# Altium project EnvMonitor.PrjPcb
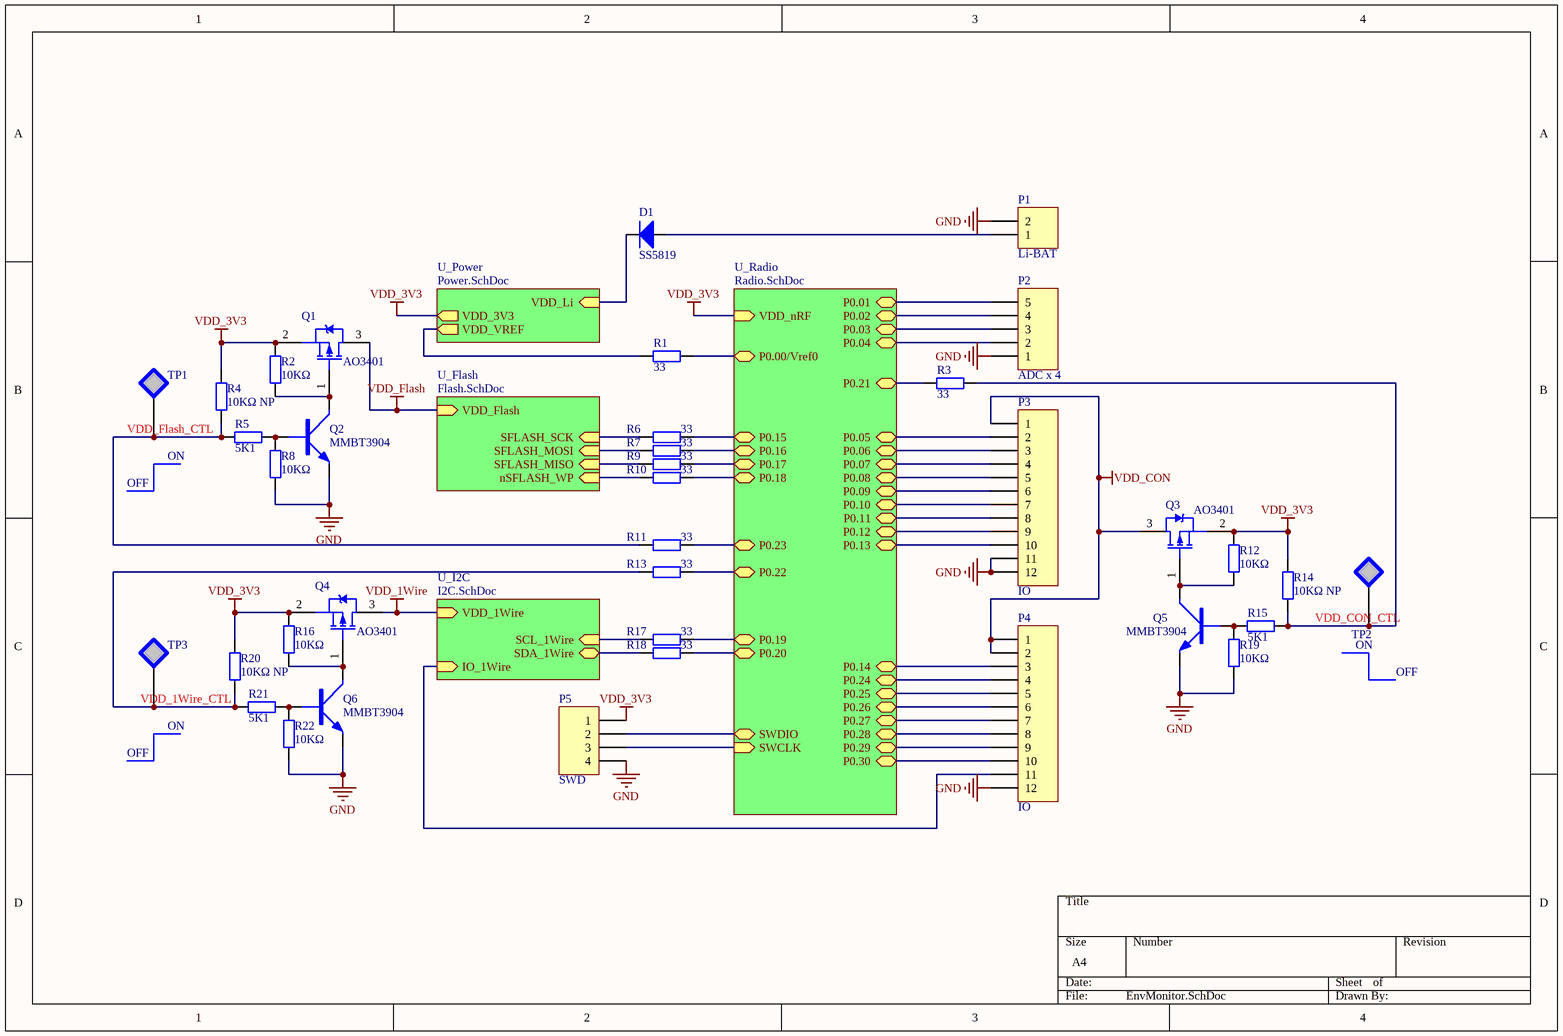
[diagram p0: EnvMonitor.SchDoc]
5 sheets, 85 parts. Net scope: hierarchical (ports join the sheet entries above them; power ports are global).
Sheets:
  EnvMonitor.SchDoc
    U_Radio = Radio.SchDoc
    U_Flash = Flash.SchDoc
    U_Power = Power.SchDoc
    U_I2C = I2C.SchDoc

## Sheet EnvMonitor.SchDoc
size A4

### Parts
D1  SS5819  [DO-41]
P1  Li-BAT  [HDR1X2]
P2  ADC x 4  [HDR1X5]
P3  IO  [HDR1X12]
P4  IO  [HDR1X12]
P5  SWD  [HDR1X4]
Q1  AO3401  [SOT23]
Q2  MMBT3904  [SOT23]
Q3  AO3401  [SOT23]
Q4  AO3401  [SOT23]
Q5  MMBT3904  [SOT23]
Q6  MMBT3904  [SOT23]
R1  33  [0603]
R2  10KΩ  [0603]
R3  33  [0603]
R4  10KΩ NP  [0603]
R5  5K1  [0603]
R6  33  [0603]
R7  33  [0603]
R8  10KΩ  [0603]
R9  33  [0603]
R10  33  [0603]
R11  33  [0603]
R12  10KΩ  [0603]
R13  33  [0603]
R14  10KΩ NP  [0603]
R15  5K1  [0603]
R16  10KΩ  [0603]
R17  33  [0603]
R18  33  [0603]
R19  10KΩ  [0603]
R20  10KΩ NP  [0603]
R21  5K1  [0603]
R22  10KΩ  [0603]
TP1  (no value)  [TP-PAD1]  (no BOM)
TP2  (no value)  [TP-PAD1]  (no BOM)
TP3  (no value)  [TP-PAD1]  (no BOM)

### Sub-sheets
U_Flash = Flash.SchDoc: SFLASH_SCK (in), SFLASH_MOSI (in), SFLASH_MISO (in), nSFLASH_WP (in), VDD_Flash (in)
U_I2C = I2C.SchDoc: VDD_1Wire (in), IO_1Wire (in), SDA_1Wire (bidir), SCL_1Wire (in)
U_Power = Power.SchDoc: VDD_Li (in), VDD_3V3 (out), VDD_VREF (out)
U_Radio = Radio.SchDoc: SWDIO (bidir), SWCLK (in), P0.00/Vref0 (bidir), P0.01 (bidir), P0.02 (bidir), P0.03 (bidir), P0.04 (bidir), P0.05 (bidir), P0.06 (bidir), P0.07 (bidir), P0.08 (bidir), P0.09 (bidir), P0.10 (bidir), P0.11 (bidir), P0.12 (bidir), P0.13 (bidir), P0.14 (bidir), P0.15 (bidir), P0.16 (bidir), P0.17 (bidir), P0.18 (bidir), P0.19 (bidir), P0.20 (bidir), P0.21 (bidir), P0.22 (bidir), P0.23 (bidir), P0.24 (bidir), P0.25 (bidir), P0.26 (bidir), P0.27 (bidir), P0.28 (bidir), P0.29 (bidir), P0.30 (bidir), VDD_nRF (in)

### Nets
GND: P1.2 P2.1 P3.11 P3.12 P4.12 P5.4 Q2.2 Q5.2 Q6.2 R8.1 R19.1 R22.1
VDD_1Wire: Q4.3(D) ; sheet U_I2C/VDD_1Wire
VDD_3V3: P5.1 Q1.2(S) Q3.2(S) Q4.2(S) R2.2 R4.2 R12.2 R14.2 R16.2 R20.2 ; sheet U_Radio/VDD_nRF, sheet U_Power/VDD_3V3
VDD_CON: P3.1 P4.1 P4.2 Q3.3(D)
VDD_Flash: Q1.3(D) ; sheet U_Flash/VDD_Flash
nSFLASH_WP: R10.2 ; sheet U_Flash/nSFLASH_WP
P0.00/Vref0: R1.1 ; sheet U_Radio/P0.00/Vref0
P0.01: P2.5 ; sheet U_Radio/P0.01
P0.02: P2.4 ; sheet U_Radio/P0.02
P0.03: P2.3 ; sheet U_Radio/P0.03
P0.04: P2.2 ; sheet U_Radio/P0.04
P0.05: P3.2 ; sheet U_Radio/P0.05
P0.06: P3.3 ; sheet U_Radio/P0.06
P0.07: P3.4 ; sheet U_Radio/P0.07
P0.08: P3.5 ; sheet U_Radio/P0.08
P0.09: P3.6 ; sheet U_Radio/P0.09
P0.10: P3.7 ; sheet U_Radio/P0.10
P0.11: P3.8 ; sheet U_Radio/P0.11
P0.12: P3.9 ; sheet U_Radio/P0.12
P0.13: P3.10 ; sheet U_Radio/P0.13
P0.14: P4.3 ; sheet U_Radio/P0.14
P0.15: R6.1 ; sheet U_Radio/P0.15
P0.16: R7.1 ; sheet U_Radio/P0.16
P0.17: R9.1 ; sheet U_Radio/P0.17
P0.18: R10.1 ; sheet U_Radio/P0.18
P0.19: R17.1 ; sheet U_Radio/P0.19
P0.20: R18.1 ; sheet U_Radio/P0.20
P0.21: R3.1 ; sheet U_Radio/P0.21
P0.22: R13.1 ; sheet U_Radio/P0.22
P0.23: R11.1 ; sheet U_Radio/P0.23
P0.24: P4.4 ; sheet U_Radio/P0.24
P0.25: P4.5 ; sheet U_Radio/P0.25
P0.26: P4.6 ; sheet U_Radio/P0.26
P0.27: P4.7 ; sheet U_Radio/P0.27
P0.28: P4.8 ; sheet U_Radio/P0.28
P0.29: P4.9 ; sheet U_Radio/P0.29
P0.30: P4.10 ; sheet U_Radio/P0.30
SFLASH_MISO: R9.2 ; sheet U_Flash/SFLASH_MISO
SFLASH_MOSI: R7.2 ; sheet U_Flash/SFLASH_MOSI
SFLASH_SCK: R6.2 ; sheet U_Flash/SFLASH_SCK
SWCLK: P5.3 ; sheet U_Radio/SWCLK
SWDIO: P5.2 ; sheet U_Radio/SWDIO
VDD_1Wire_CTL: R13.2 R20.1 R21.2 TP3.1
VDD_CON_CTL: R3.2 R14.1 R15.2 TP2.1
VDD_Flash_CTL: R4.1 R5.2 R11.2 TP1.1
VDD_Li: D1.2(K) ; sheet U_Power/VDD_Li
VDD_VREF: R1.2 ; sheet U_Power/VDD_VREF
NetD1_1: D1.1(A) P1.1
NetP4_11: P4.11 ; sheet U_I2C/IO_1Wire
NetQ1_1: Q1.1(G) Q2.3 R2.1
NetQ2_1: Q2.1 R5.1 R8.2
NetQ3_1: Q3.1(G) Q5.3 R12.1
NetQ4_1: Q4.1(G) Q6.3 R16.1
NetQ5_1: Q5.1 R15.1 R19.2
NetQ6_1: Q6.1 R21.1 R22.2
NetR17_2: R17.2 ; sheet U_I2C/SCL_1Wire
NetR18_2: R18.2 ; sheet U_I2C/SDA_1Wire

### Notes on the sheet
- OFF
- ON

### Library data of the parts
D1 = Diode 1N4001: 1 Amp General Purpose Rectifier
P1 = Header 2: Header, 2-Pin
P2 = Header 5: Header, 5-Pin
P3 P4 = Header 12: Header, 12-Pin
P5 = Header 4: Header, 4-Pin
Q1 Q3 Q4 = DMP3098L: -30V,-3.8A   PMOS  70-120mΩ; Manufacturer: DIODES; Kind: 贴片MOS管; Remark: 关键元器件
Q2 Q5 Q6 = 9013: NPN三极管; Kind: 贴片三极管
R1-R22 = RES_0603: RES 10KΩ 1/10w  5% SMT 0603
TP1-TP3 = TESTPOINT: Test Point

## Sheet Radio.SchDoc: PCA100024 - Radio
size A4; Revision: 1.0.0; SheetNumber: 1; SheetTotal: 3; DrawnBy: RUBR; ProjectNumber: 4400; PCBRevision: 0141RUBR; DocumentSize: A4; PCAName: PCA10024; PCBNumber: 400081
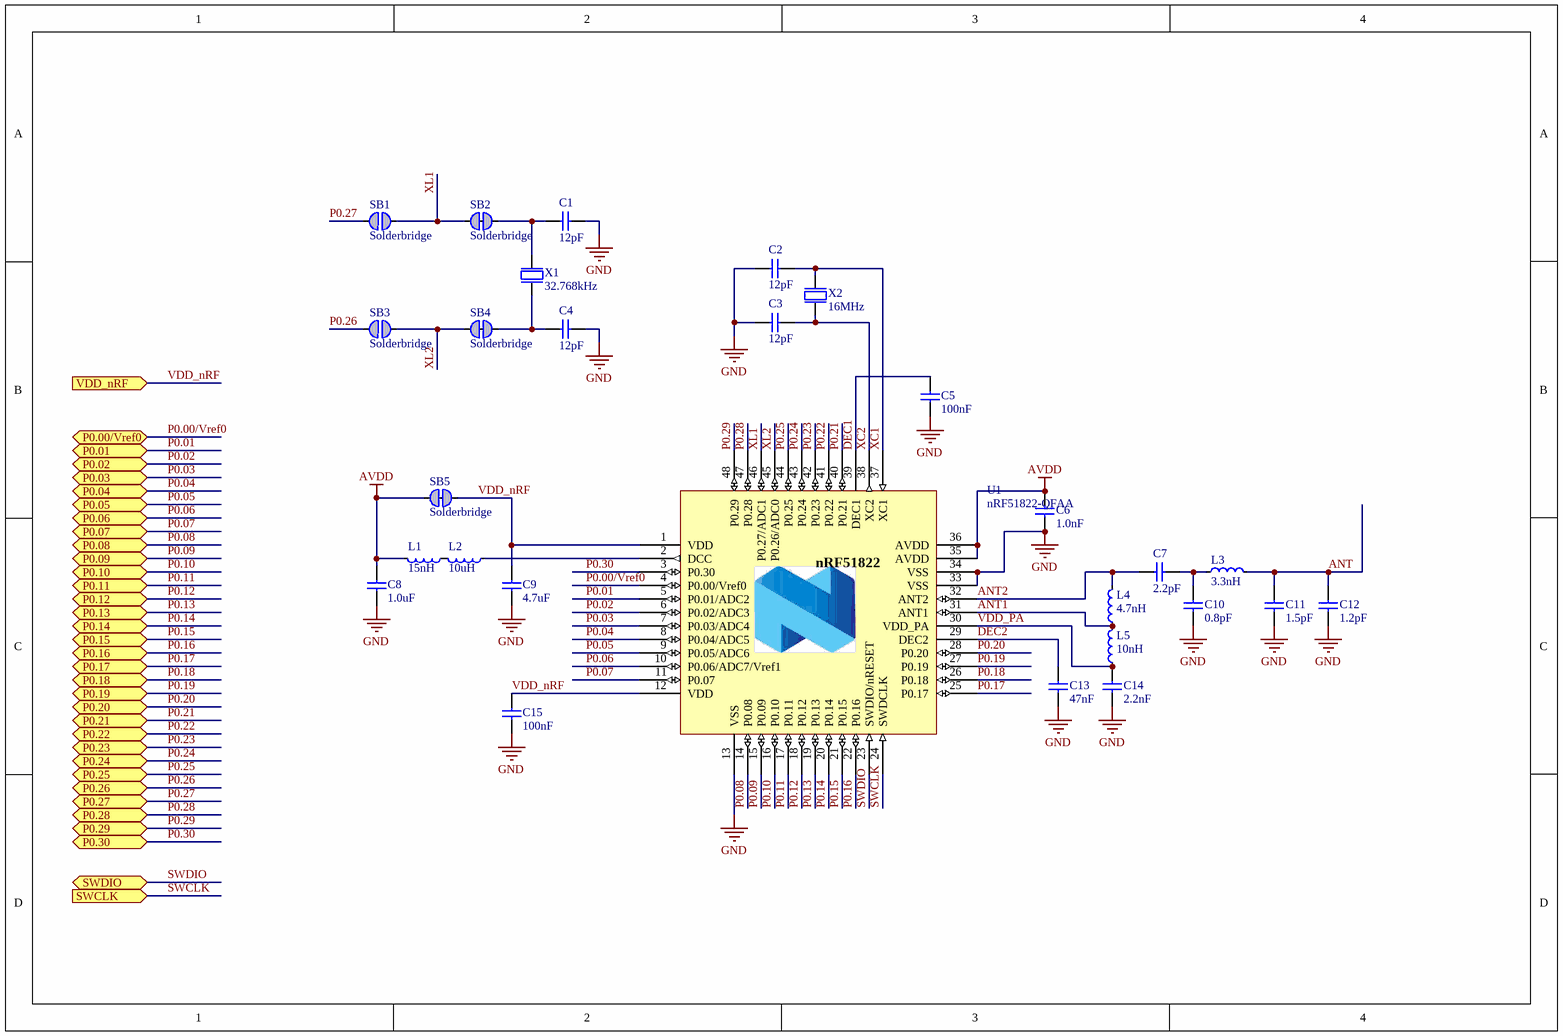
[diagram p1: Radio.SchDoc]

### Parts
C1  12pF  [CAPC1005X04L]
C2  12pF  [CAPC1005X04L]
C3  12pF  [CAPC1005X04L]
C4  12pF  [CAPC1005X04L]
C5  100nF  [CAPC1005X04L]
C6  1.0nF  [CAPC1005X04L]
C7  2.2pF  [CAPC1005X04L]
C8  1.0uF  [CAPC1608X06L]
C9  4.7uF  [CAPC1608X06L]
C10  0.8pF  [CAPC1005X04L]
C11  1.5pF  [CAPC1005X04L]
C12  1.2pF  [CAPC1005X04L]
C13  47nF  [CAPC1005X04L]
C14  2.2nF  [CAPC1005X04L]
C15  100nF  [CAPC1005X04L]
L1  15nH  [INDC1005X04L]
L2  10uH  [INDC1608X06L]
L3  3.3nH  [INDC1005X04L]
L4  4.7nH  [INDC1005X04L]
L5  10nH  [INDC1005X04L]
SB1  Solderbridge  [Solderbridge]  (no BOM)
SB2  Solderbridge  [Solderbridge_Shorted]  (net tie, no BOM)
SB3  Solderbridge  [Solderbridge]  (no BOM)
SB4  Solderbridge  [Solderbridge_Shorted]  (net tie, no BOM)
SB5  Solderbridge  [Solderbridge_Shorted]  (net tie, no BOM)
U1  nRF51822-QFAA  [QFN40P600X600X90-48N]
X1  32.768kHz  [FC-135]
X2  16MHz  [BT-XTAL_2520]

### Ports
P0.00/Vref0 (bidir), P0.01 (bidir), P0.02 (bidir), P0.03 (bidir), P0.04 (bidir), P0.05 (bidir), P0.06 (bidir), P0.07 (bidir), P0.08 (bidir), P0.09 (bidir), P0.10 (bidir), P0.11 (bidir), P0.12 (bidir), P0.13 (bidir), P0.14 (bidir), P0.15 (bidir), P0.16 (bidir), P0.17 (bidir), P0.18 (bidir), P0.19 (bidir), P0.20 (bidir), P0.21 (bidir), P0.22 (bidir), P0.23 (bidir), P0.24 (bidir), P0.25 (bidir), P0.26 (bidir), P0.27 (bidir), P0.28 (bidir), P0.29 (bidir), P0.30 (bidir), SWCLK (in), SWDIO (bidir), VDD_nRF (in)

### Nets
AVDD: C6.1 C8.2 L1.2 SB5.2 U1.35(AVDD) U1.36(AVDD)
GND: C1.2 C2.2 C3.2 C4.2 C5.2 C6.2 C8.1 C9.2 C10.2 C11.2 C12.2 C13.2 C14.2 C15.2 U1.13(VSS) U1.33(VSS) U1.34(VSS) U1.49 X2.2(GND) X2.4(GND)
VDD_nRF: C9.1 C15.1 SB5.1 U1.1(VDD) U1.12(VDD) ; port VDD_nRF  [project net VDD_3V3]
ANT: C11.1 C12.1 L3.2
ANT1: L4.1 L5.2 U1.31(ANT1)
ANT2: C7.1 L4.2 U1.32(ANT2)
DEC1: C5.1 U1.39(DEC1)
DEC2: C13.1 U1.29(DEC2)
P0.00/Vref0: U1.4(P0.00/Vref0) ; port P0.00/Vref0
P0.01: U1.5(P0.01/ADC2) ; port P0.01
P0.02: U1.6(P0.02/ADC3) ; port P0.02
P0.03: U1.7(P0.03/ADC4) ; port P0.03
P0.04: U1.8(P0.04/ADC5) ; port P0.04
P0.05: U1.9(P0.05/ADC6) ; port P0.05
P0.06: U1.10(P0.06/ADC7/Vref1) ; port P0.06
P0.07: U1.11(P0.07) ; port P0.07
P0.08: U1.14(P0.08) ; port P0.08
P0.09: U1.15(P0.09) ; port P0.09
P0.10: U1.16(P0.10) ; port P0.10
P0.11: U1.17(P0.11) ; port P0.11
P0.12: U1.18(P0.12) ; port P0.12
P0.13: U1.19(P0.13) ; port P0.13
P0.14: U1.20(P0.14) ; port P0.14
P0.15: U1.21(P0.15) ; port P0.15
P0.16: U1.22(P0.16) ; port P0.16
P0.17: U1.25(P0.17) ; port P0.17
P0.18: U1.26(P0.18) ; port P0.18
P0.19: U1.27(P0.19) ; port P0.19
P0.20: U1.28(P0.20) ; port P0.20
P0.21: U1.40(P0.21) ; port P0.21
P0.22: U1.41(P0.22) ; port P0.22
P0.23: U1.42(P0.23) ; port P0.23
P0.24: U1.43(P0.24) ; port P0.24
P0.25: U1.44(P0.25) ; port P0.25
P0.26: SB3.2 ; port P0.26
P0.27: SB1.2 ; port P0.27
P0.28: U1.47(P0.28) ; port P0.28
P0.29: U1.48(P0.29) ; port P0.29
P0.30: U1.3(P0.30) ; port P0.30
SWCLK: U1.24(SWDCLK) ; port SWCLK
SWDIO: U1.23(SWDIO/nRESET) ; port SWDIO
VDD_PA: C14.1 L5.1 U1.30(VDD_PA)
XC1: C2.1 U1.37(XC1) X2.1(inp)
XC2: C3.1 U1.38(XC2) X2.3(out)
XL1: SB1.1 SB2.2 U1.46(P0.27/ADC1)
XL2: SB3.1 SB4.2 U1.45(P0.26/ADC0)
NetC1_1: C1.1 SB2.1 X1.2(out)
NetC4_1: C4.1 SB4.1 X1.1(inp)
NetC7_2: C7.2 C10.1 L3.1
NetL1_1: L1.1 L2.2
NetL2_1: L2.1 U1.2(DCC)

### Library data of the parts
C1-C4 = C0402-12p: Capacitor, NP0, ?%; Note: 50V; Artikkelnr Noca: 20029159
C5 C15 = C0402-100n: Capacitor, X7R, ?0%; Note: 16V; Artikkelnr Noca: 20039200
C6 = C0402-1n0: Capacitor, X7R, ?0%; Note: 50V; Artikkelnr Noca: 20039223
C7 = C0402-2.2p: Capacitor, NP0, ?.1pF; Note: 50V; Artikkelnr Noca: 20029145
C8 = C0603-1?: Capacitor, X7R, ?0%; Value: 1.0µF; Note: 16V; Artikkelnr Noca: 20039335
C9 = C0603-4?: Capacitor, X5R, ?0%; Value: 4.7µF; Note: 6.3V; Artikkelnr Noca: 20069060
C10 = C0402-0.8p: Capacitor, NP0, ?%; Note: 50V; Artikkelnr Noca: 20029147
C11 = C0402-1.5p: Capacitor, NP0, ?.1pF; Note: 50V; Artikkelnr Noca: 20029139
C12 = C0402-1.2p: Capacitor, NP0, ?.1pF; Note: 50V; Artikkelnr Noca: 20029157
C13 = C0402-47n: Capacitor, X7R, ?0%; Note: Chip Cap 10%; Artikkelnr Noca: 20039389
C14 = C0402-2n2: Capacitor, X7R, ?0%; Note: 50V; Artikkelnr Noca: 20039221
L1 = L0402-15n: Inductor, 320mA, ?%; Manufacturer: Taiyo Yuden; Manufacturer Part Number: HK100515NJ-T; 2nd source part number: 658-1328; Note: High frequency chip inductor ?0%; Artikkelnr Noca: 33029323
L2 = L0603-10?: Inductor, 80mA, ?0%; Part Number: L0603-10µ|ISHIDDEN=T; Manufacturer: Taiyo Yuden; Manufacturer Part Number: LBMF1608T100K; 2nd source part number: 178-6105; Value: 10µH; Note: LBMF1608T100K 10µH 80mA 0603; Artikkelnr Noca: 33029314
L3 = L0402-3n3: Inductor, 190mA, ?.1nH; Manufacturer: Murata; Manufacturer Part Number: LQP15MN3N3B02D; Note: High frequency chip inductor ?%; Artikkelnr Noca: 33029369
L4 = L0402-4n7: Inductor, 160mA, ?.1nH; Manufacturer: Murata; Manufacturer Part Number: LQP15MN4N7B02D; Note: High frequency chip inductor ?%; Artikkelnr Noca: 33029164
L5 = L0402-10n: Inductor, 100mA, ?%; Manufacturer: Murata; Manufacturer Part Number: LQP15MN10NG02D; Note: High frequency chip inductor ?%; Artikkelnr Noca: 33029425
SB1 SB3 = Solderbridge: Artikkelnr Noca: N.A.
SB2 SB4 SB5 = Solderbridge Shorted: Shorted Solderbridge; Artikkelnr Noca: N.A.
U1 = nRF51822_QFAA: Multi-protocol Bluetooth Low Energy and 2.4GHz proprietary system-on-chip; Part Number: nRF51822-QFAA-XLR2.4; Manufacturer: Nordic Semiconductor; Manufacturer Part Number: nRF51822-QFAAGx; Note: nRF51822 - QFN48 6x6 0.4mm pitch; Artikkelnr Noca: 15079242
X1 = XTAL_FC-135 32.768k: EPSON TOYOCOM - FC-135 32.768KHZ ?0PPM,9.0PF - CRYSTAL, SM, WATCH; 2nd source part number: 127-8037; Note: XTAL SMD 32.768kHz, 3215; Artikkelnr Noca: 22019091
X2 = NX2520SA-16MHZ-STD-CSW-5: XTAL SMD 2520, 16MHz, 8pF, ?5ppm; Manufacturer: NDK; Note: XTAL SMD 16.000MHz; Artikkelnr Noca: 22019192

## Sheet Flash.SchDoc
size A4
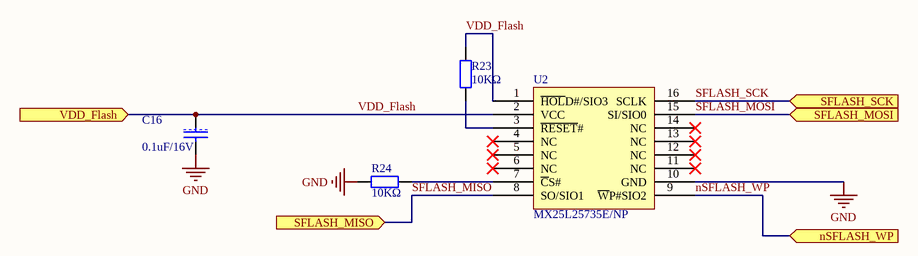
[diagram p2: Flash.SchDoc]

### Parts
C16  0.1uF/16V  [0603]  (no BOM)
R23  10KΩ  [0603]
R24  10KΩ  [0603]
U2  MX25L25735E/NP  [SOIC16W]  (no BOM)

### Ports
nSFLASH_WP (in), SFLASH_MISO (in), SFLASH_MOSI (in), SFLASH_SCK (in), VDD_Flash (in)

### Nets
GND: C16.2 R24.2 U2.10(GND)
VDD_Flash: C16.1 R23.2 U2.1(~{HOL}D#/SIO3) U2.2(VCC) ; port VDD_Flash
nSFLASH_WP: U2.9(~{W}P#SIO2) ; port nSFLASH_WP
SFLASH_MISO: U2.8(SO/SIO1) ; port SFLASH_MISO
SFLASH_MOSI: U2.15(SI/SIO0) ; port SFLASH_MOSI
SFLASH_SCK: U2.16(SCLK) ; port SFLASH_SCK
NetR23_1: R23.1 U2.3(~{RESET}#)
NetR24_1: R24.1 U2.7(~{C}S#)

Not connected (* = marked no-connect by the designer): U2 4(NC)* 5(NC)* 6(NC)* 11(NC)* 12(NC)* 13(NC)* 14(NC)*

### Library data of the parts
C16 = CAP: 贴片陶瓷电容
R23 R24 = RES_0603: RES 10KΩ 1/10w  5% SMT 0603
U2 = MX25L25735E: SPI_flash; Manufacturer: MXIC; Kind: 集成电路; Remark: 关键元器件; 规格: 16-PIN SOP(300mil)

## Sheet Power.SchDoc
size A4
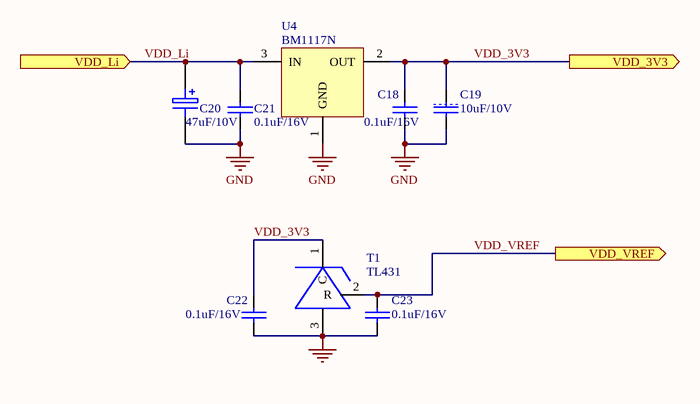
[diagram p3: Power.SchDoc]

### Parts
C18  0.1uF/16V  [0603]
C19  10uF/10V  [0805]
C20  47uF/10V  [3528]
C21  0.1uF/16V  [0603]
C22  0.1uF/16V  [0603]
C23  0.1uF/16V  [0603]
T1  TL431  [so-8]
U4  BM1117N  [TO-252]

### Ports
VDD_3V3 (out), VDD_Li (in), VDD_VREF (out)

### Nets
GND: C18.2 C19.2 C20.2 C21.2 C22.2 C23.2 T1.3 U4.1(GND)
VDD_3V3: C18.1 C19.1 C22.1 T1.1(C) U4.2(OUT) ; port VDD_3V3
VDD_Li: C20.1 C21.1 U4.3(IN) ; port VDD_Li
VDD_VREF: C23.1 T1.2(R) ; port VDD_VREF

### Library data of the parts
C18 C19 C21-C23 = CAP: 贴片陶瓷电容
C20 = ELECTRO1: 贴片陶瓷电容; Kind: 直插电解电容
U4 = AZ1084

## Sheet I2C.SchDoc
size A4
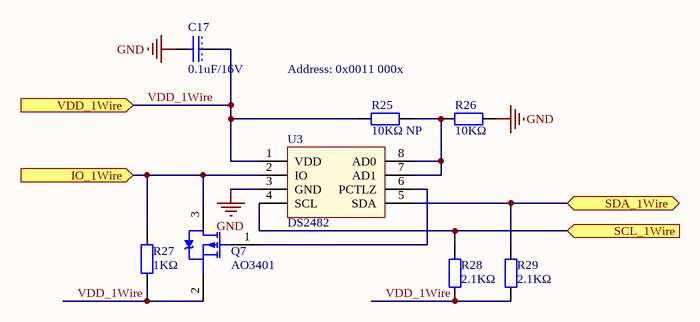
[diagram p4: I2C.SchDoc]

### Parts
C17  0.1uF/16V  [0603]  (no BOM)
Q7  AO3401  [SOT23]
R25  10KΩ NP  [0603]
R26  10KΩ  [0603]
R27  1KΩ  [0603]
R28  2.1KΩ  [0603]
R29  2.1KΩ  [0603]
U3  DS2482

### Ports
IO_1Wire (in), SCL_1Wire (in), SDA_1Wire (bidir), VDD_1Wire (in)

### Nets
GND: C17.2 R26.1 U3.3(GND)
VDD_1Wire: C17.1 Q7.2(S) R25.2 R27.1 R28.2 R29.2 U3.1(VDD) ; port VDD_1Wire
NetP4_11: Q7.3(D) R27.2 U3.2(IO) ; port IO_1Wire
NetQ7_1: Q7.1(G) U3.6(PCTLZ)
NetR17_2: R28.1 U3.4(SCL) ; port SCL_1Wire
NetR18_2: R29.1 U3.5(SDA) ; port SDA_1Wire
NetR25_1: R25.1 R26.2 U3.7(AD1) U3.8(AD0)

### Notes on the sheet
- Address: 0x0011 000x

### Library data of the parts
C17 = CAP: 贴片陶瓷电容
Q7 = DMP3098L: as Q1 on sheet EnvMonitor
R25-R29 = RES_0603: RES 10KΩ 1/10w  5% SMT 0603

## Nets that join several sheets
GND: EnvMonitor (12 pins), Radio (20 pins), Flash (C16.2 R24.2 U2.10), Power (8 pins), I2C (C17.2 R26.1 U3.3)
VDD_1Wire: EnvMonitor (Q4.3), I2C (7 pins)
VDD_3V3: EnvMonitor (10 pins), Radio (5 pins), Power (5 pins)
VDD_Flash: EnvMonitor (Q1.3), Flash (C16.1 R23.2 U2.1 U2.2)
NetP4_11: EnvMonitor (P4.11), I2C (Q7.3 R27.2 U3.2)
NetR17_2: EnvMonitor (R17.2), I2C (R28.1 U3.4)
NetR18_2: EnvMonitor (R18.2), I2C (R29.1 U3.5)
nSFLASH_WP: EnvMonitor (R10.2), Flash (U2.9)
P0.00/Vref0: EnvMonitor (R1.1), Radio (U1.4)
P0.01: EnvMonitor (P2.5), Radio (U1.5)
P0.02: EnvMonitor (P2.4), Radio (U1.6)
P0.03: EnvMonitor (P2.3), Radio (U1.7)
P0.04: EnvMonitor (P2.2), Radio (U1.8)
P0.05: EnvMonitor (P3.2), Radio (U1.9)
P0.06: EnvMonitor (P3.3), Radio (U1.10)
P0.07: EnvMonitor (P3.4), Radio (U1.11)
P0.08: EnvMonitor (P3.5), Radio (U1.14)
P0.09: EnvMonitor (P3.6), Radio (U1.15)
P0.10: EnvMonitor (P3.7), Radio (U1.16)
P0.11: EnvMonitor (P3.8), Radio (U1.17)
P0.12: EnvMonitor (P3.9), Radio (U1.18)
P0.13: EnvMonitor (P3.10), Radio (U1.19)
P0.14: EnvMonitor (P4.3), Radio (U1.20)
P0.15: EnvMonitor (R6.1), Radio (U1.21)
P0.16: EnvMonitor (R7.1), Radio (U1.22)
P0.17: EnvMonitor (R9.1), Radio (U1.25)
P0.18: EnvMonitor (R10.1), Radio (U1.26)
P0.19: EnvMonitor (R17.1), Radio (U1.27)
P0.20: EnvMonitor (R18.1), Radio (U1.28)
P0.21: EnvMonitor (R3.1), Radio (U1.40)
P0.22: EnvMonitor (R13.1), Radio (U1.41)
P0.23: EnvMonitor (R11.1), Radio (U1.42)
P0.24: EnvMonitor (P4.4), Radio (U1.43)
P0.25: EnvMonitor (P4.5), Radio (U1.44)
P0.26: EnvMonitor (P4.6), Radio (SB3.2)
P0.27: EnvMonitor (P4.7), Radio (SB1.2)
P0.28: EnvMonitor (P4.8), Radio (U1.47)
P0.29: EnvMonitor (P4.9), Radio (U1.48)
P0.30: EnvMonitor (P4.10), Radio (U1.3)
SFLASH_MISO: EnvMonitor (R9.2), Flash (U2.8)
SFLASH_MOSI: EnvMonitor (R7.2), Flash (U2.15)
SFLASH_SCK: EnvMonitor (R6.2), Flash (U2.16)
SWCLK: EnvMonitor (P5.3), Radio (U1.24)
SWDIO: EnvMonitor (P5.2), Radio (U1.23)
VDD_Li: EnvMonitor (D1.2), Power (C20.1 C21.1 U4.3)
VDD_VREF: EnvMonitor (R1.2), Power (C23.1 T1.2)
